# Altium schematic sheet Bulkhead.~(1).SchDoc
size B; Organization: Monterey Bay Aquarium Research Institute; Address1: 7700 Sandholdt Rd; Address2: Moss Landing, CA 95039-9644; CompanyName: MBARI
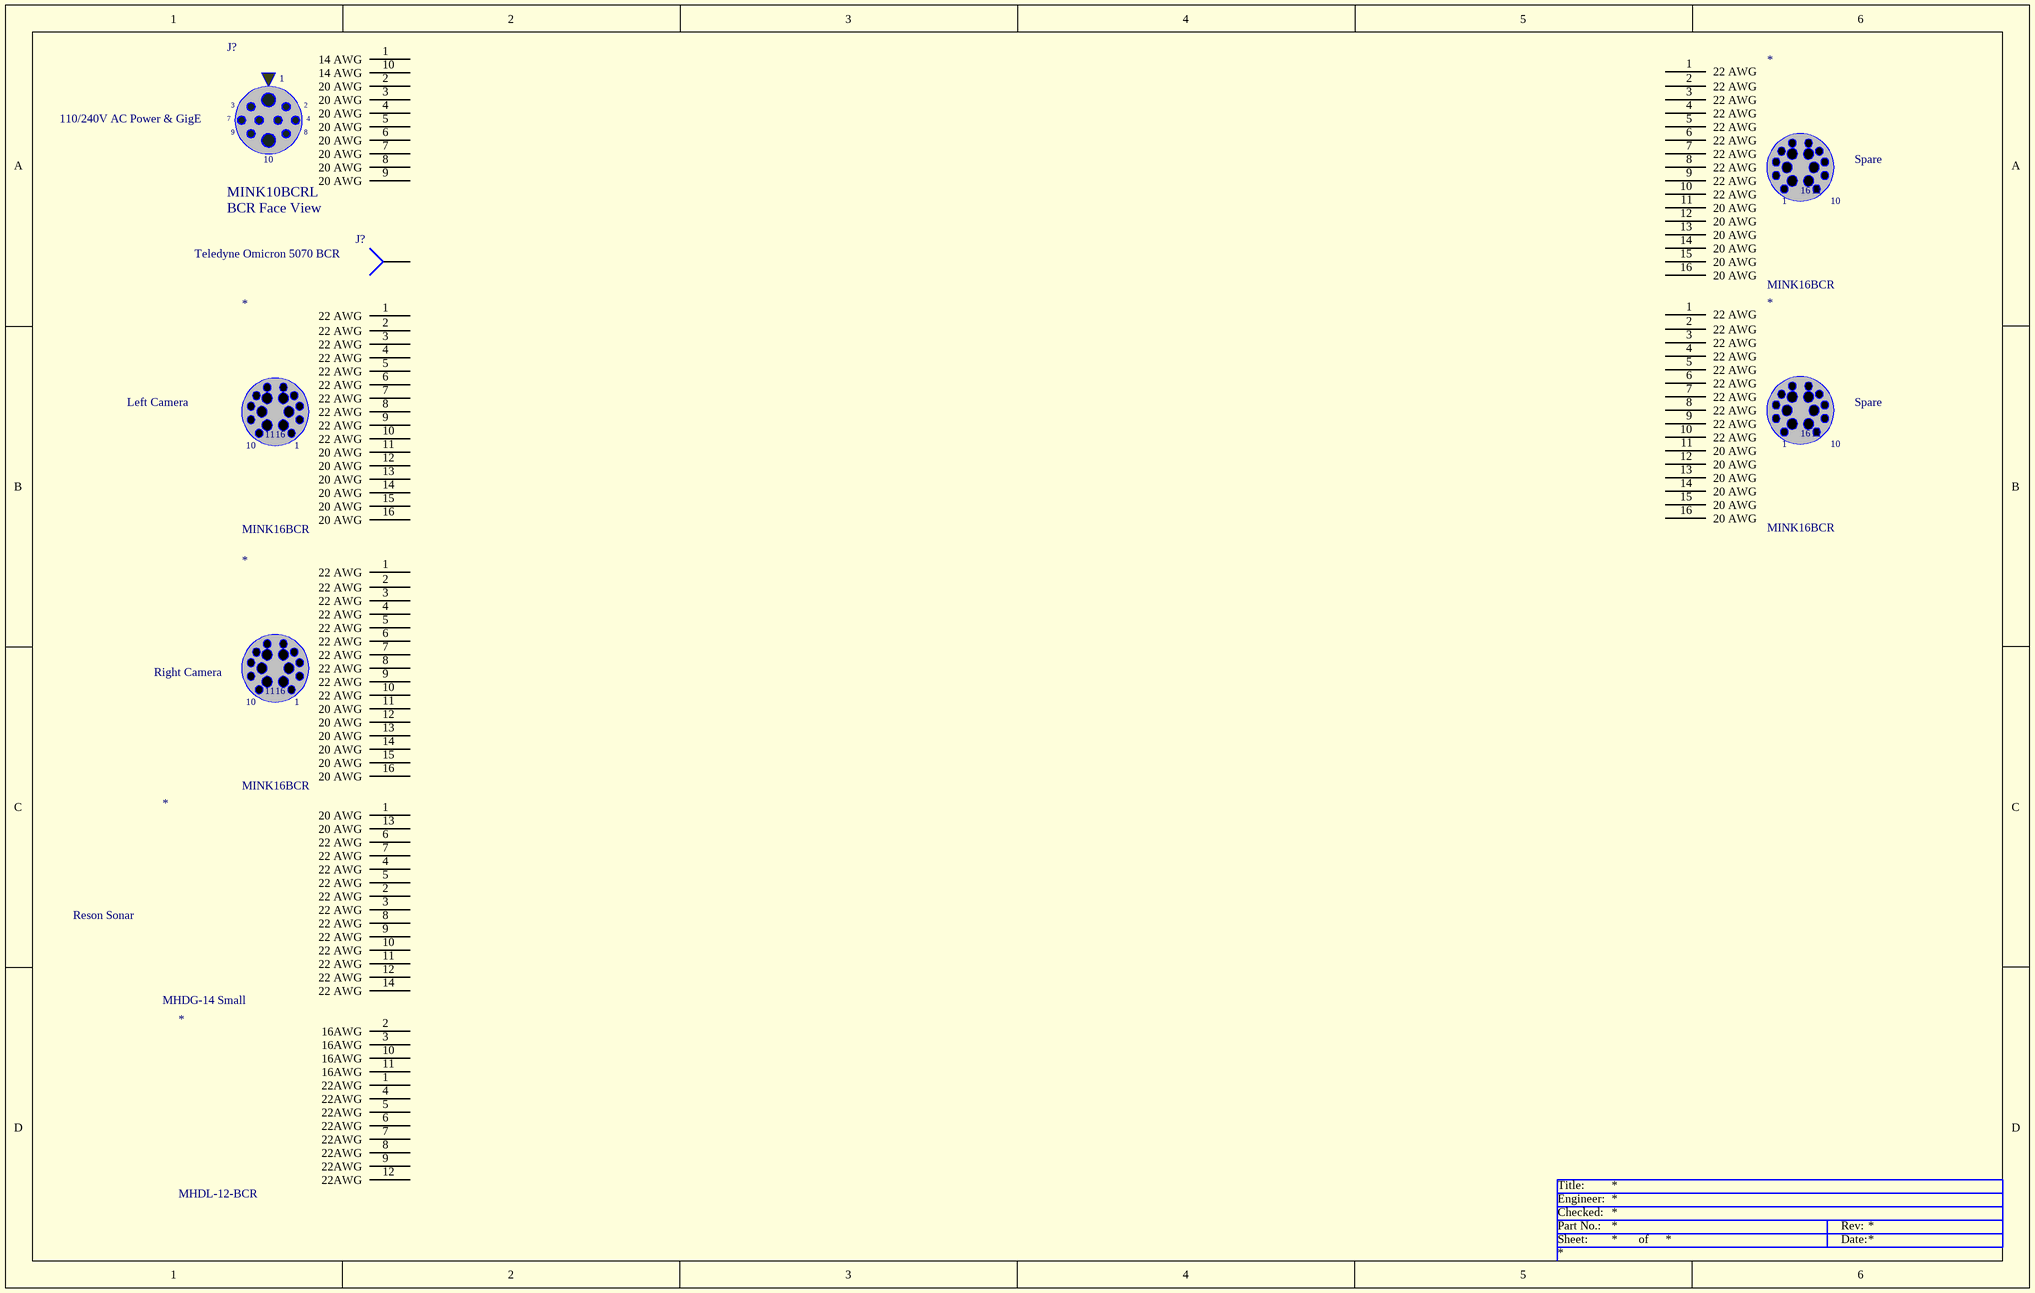
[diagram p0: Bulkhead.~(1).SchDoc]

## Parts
(Parts that share a designator on the sheet are numbered #1, #2 ... from top to bottom, then left to right.)
*#1  MINK16BCR
*#2  MINK16BCR
*#3  MINK16BCR
*#4  MINK16BCR
*#5  MHDG-14 Small
*#6  MHDL-12-BCR
J?#1  MINK10BCRL  View: BCR Face View
J?#2  Teledyne Omicron 5070 BCR  [PIN1]

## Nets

Not connected (* = marked no-connect by the designer): *#1 1(22_AWG) 2(22_AWG) 3(22_AWG) 4(22_AWG) 5(22_AWG) 6(22_AWG) 7(22_AWG) 8(22_AWG) 9(22_AWG) 10(22_AWG) 11(20_AWG) 12(20_AWG) 13(20_AWG) 14(20_AWG) 15(20_AWG) 16(20_AWG); *#2 1(22_AWG) 2(22_AWG) 3(22_AWG) 4(22_AWG) 5(22_AWG) 6(22_AWG) 7(22_AWG) 8(22_AWG) 9(22_AWG) 10(22_AWG) 11(20_AWG) 12(20_AWG) 13(20_AWG) 14(20_AWG) 15(20_AWG) 16(20_AWG); *#3 1(22_AWG) 2(22_AWG) 3(22_AWG) 4(22_AWG) 5(22_AWG) 6(22_AWG) 7(22_AWG) 8(22_AWG) 9(22_AWG) 10(22_AWG) 11(20_AWG) 12(20_AWG) 13(20_AWG) 14(20_AWG) 15(20_AWG) 16(20_AWG); *#4 1(22_AWG) 2(22_AWG) 3(22_AWG) 4(22_AWG) 5(22_AWG) 6(22_AWG) 7(22_AWG) 8(22_AWG) 9(22_AWG) 10(22_AWG) 11(20_AWG) 12(20_AWG) 13(20_AWG) 14(20_AWG) 15(20_AWG) 16(20_AWG); *#5 1(20_AWG) 2(22_AWG) 3(22_AWG) 4(22_AWG) 5(22_AWG) 6(22_AWG) 7(22_AWG) 8(22_AWG) 9(22_AWG) 10(22_AWG) 11(22_AWG) 12(22_AWG) 13(20_AWG) 14(22_AWG); *#6 1(22AWG) 2(16AWG) 3(16AWG) 4(22AWG) 5(22AWG) 6(22AWG) 7(22AWG) 8(22AWG) 9(22AWG) 10(16AWG) 11(16AWG) 12(22AWG); J?#1 1(14_AWG) 2(20_AWG) 3(20_AWG) 4(20_AWG) 5(20_AWG) 6(20_AWG) 7(20_AWG) 8(20_AWG) 9(20_AWG) 10(14_AWG); J?#2 1

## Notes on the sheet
- 110/240V AC Power & GigE
- Spare
- Left Camera
- Right Camera
- Reson Sonar

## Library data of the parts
*#1-*#4 = SEACON-MINK-16-FCR: Seacon MINK-16 FCR
*#6 = MHDL-12-BCR: Impulse MHDL12 BCR
J?#1 = SEACON-MINK-10/L CCR (SMALL): Seacon MINK-10/L-CCR Molded to C/F Falmat Cable
J?#2 = Socket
